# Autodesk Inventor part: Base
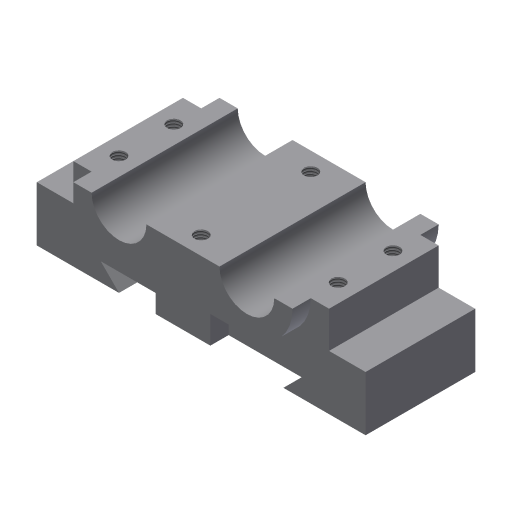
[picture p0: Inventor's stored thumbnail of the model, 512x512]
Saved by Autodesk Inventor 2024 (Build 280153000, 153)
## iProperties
Shininess: 77.0
Length Units: 11269
Angle Units: 11279
Time Units: 11290
Mass Units: 11283
Length Display Precision: 3
Angle Display Precision: 2
Created: 2002-02
Part Number: Base
Document SubType Name: Modeling
Designer: ***
Density: 1 g/cm^3
Material: Generic
Appearance: Default
Density: 0.0
Volumn: 0.0
Area: 0.0
PropertySet Name: Model Information
Control State: 0
Master: False
Checked Out: False
Author: ***
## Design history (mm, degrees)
sketch "Sketch2"
  geometry: L1 (-10.066, -1.263)-(24.934, -1.263); L2 (37.434, 11.237)-(32.434, 11.237); L3 (17.434, 11.237)-(-2.566, 11.237); L4 (-17.566, 11.237)-(-22.566, 11.237); A1 r 12.5 centre (-10.066, 11.237) between (-22.566, 11.237) and (-10.066, -1.263); A2 r 12.5 centre (24.934, 11.237) between (24.934, -1.263) and (37.434, 11.237); A3 r 7.5 centre (24.934, 11.237) between (17.434, 11.237) and (32.434, 11.237); A4 r 7.5 centre (-10.066, 11.237) between (-17.566, 11.237) and (-2.566, 11.237)
  constraints: 8 end point, 8 point on circle, 4 centre point, 3 horizontal, 3 parallel, 2 coincident, 2 equal radius, 2 tangent
  dimensions: "d0" = 12.5 radius of A1; "d1" = 7.5 radius of A4; "d2" = 35 distance of A1.centre A2.centre; "d3" = 12.5 distance between parallel lines of L3 L1
extrude "Extrusion1" new body sketch "Sketch2" stored distance "d4" = 40; taper "d5" = 0 deg
sketch "Sketch4"
  geometry: L1 (-27.566, 1.237)-(-37.566, 1.237); L2 (-37.566, 1.237)-(-37.566, -13.763); L3 (-37.566, -13.763)-(-15.066, -13.763); L4 (-15.066, -13.763)-(-20.066, -8.763); L5 (-20.066, -8.763)-(34.934, -8.763); L6 (34.934, -8.763)-(29.934, -13.763); L7 (29.934, -13.763)-(52.434, -13.763); L8 (52.434, -13.763)-(52.434, 1.237); L9 (52.434, 1.237)-(42.434, 1.237); L10 (24.934, -1.263)-(-10.066, -1.263); L11 (-17.566, 11.237)-(-22.566, 11.237) reference; L12 (37.434, 11.237)-(32.434, 11.237) reference; L13 (-22.566, 11.237)-(-27.566, 11.237); L14 (-27.566, 11.237)-(-27.566, 1.237); L15 (37.434, 11.237)-(42.434, 11.237); L16 (42.434, 11.237)-(42.434, 1.237); A1 r 12.5 centre (24.934, 11.237) between (24.934, -1.263) and (37.434, 11.237); A2 r 12.5 centre (-10.066, 11.237) between (-22.566, 11.237) and (-10.066, -1.263); A3 r 12.5 centre (24.934, 11.237) between (24.934, -1.263) and (37.434, 11.237) reference; A4 r 12.5 centre (-10.066, 11.237) between (-22.566, 11.237) and (-10.066, -1.263) reference
  constraints: 28 end point, 6 perpendicular, 5 equal length, 4 concentric, 4 parallel, 4 point on circle, 2 centre point, 2 collinear, 1 tangent
  dimensions: "d12" = 15 distance of L1.end L2.end; "d13" = 25 distance from line of L3 L11.end; "d14" = 90 distance between parallel lines of L2 L8; "d15" = 5 distance between parallel lines of L5 L7; "d16" = 22.5 distance of L2.end L3.end; "d24" = 5 distance of L12.start L15.end; "d25" = 15 distance from line of L8 L12.start
extrude "Extrusion3" join sketch "Sketch4" stored distance "d17" = 30; taper "d18" = 0 deg
sketch "Sketch5"
  geometry: L1 (-14.934, -1.263)-(0.066, -1.263); L2 (0.066, -1.263)-(0.066, -8.763); L3 (0.066, -8.763)-(-14.934, -8.763); L4 (-14.934, -8.763)-(-14.934, -1.263); L5 (10.066, -1.263)-(-24.934, -1.263) reference; 1 further point
  constraints: 8 end point, 2 parallel, 1 collinear, 1 horizontal, 1 perpendicular
  dimensions: "d19" = 7.5 distance of L1.end L2.end; "d20" = 15 distance of L2.end L3.end; "d21" = 15 distance from line of point (-29.934, -13.763) L4
extrude "Extrusion4" join sketch "Sketch5" distance "d22" = 40; taper "d23" = 0 deg
sketch "Sketch6"
  geometry: L1 (-5, -35)-(0, -35) reference; L2 (-5, -35)-(-5, -5) reference; 1 further point
  dimensions: "d26" = 7.5 distance from line of L1 point (0, -27.5); "d27" = 5 distance from line of L2 point (0, -27.5)
hole "Hole1" sketch "Sketch6" diameter "d28" = 3.688; stored, may be unused: countersink angle "d32" = 82 deg, drill point angle "d34" = 0 deg; dims "d29" = 9, "d30" = 4, "d31" = 2, "d33" = 15
pattern_linear "Rectangular Pattern1" dims "d37" = 60, "d40" = 15
sketch "Sketch7"
  geometry: L1 (-20, -40)-(-20, -35) reference; L2 (0, -40)-(20, -40) reference; 1 further point
  dimensions: "d41" = 30 distance from line of L1 point (10, -35); "d42" = 5 distance from line of L2 point (10, -35)
hole "Hole2" sketch "Sketch7" diameter "d43" = 3.688; stored, may be unused: countersink angle "d47" = 82 deg, drill point angle "d49" = 0 deg; dims "d44" = 9, "d45" = 4, "d46" = 2, "d48" = 15
pattern_linear "Rectangular Pattern2" dims "d52" = 30
body "Solid1"
